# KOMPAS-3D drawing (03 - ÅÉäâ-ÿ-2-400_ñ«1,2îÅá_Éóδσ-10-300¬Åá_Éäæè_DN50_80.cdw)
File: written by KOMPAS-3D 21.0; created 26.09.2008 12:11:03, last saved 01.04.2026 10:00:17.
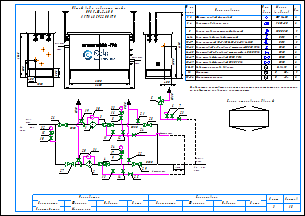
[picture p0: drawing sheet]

Sheets 1-2: A3, landscape

Document properties: Наименование: Макро:21; Автор: RaskoAdmin; Форматы листов документа: 2xA3; Полное имя файла: \\UR38nt01\Departments\КТО\КБ ПУРДГ\Заявки\Прайс-лист на типовые шкафы ГРПШ\ПРДГ_стандарт_20_03_2026\ПРДГ с РДСК\ПРДГ-Ш-2-400_до1,2МПа_Рвых-10-300кПа_РДСК_DN50_80.cdw

Title block, sheet 1: Наименование: Пункт учета газа / ПУГ-Ш-400-Р / ЛГТИ.485922.001ТУ; designation: ЛГТИ.03.4411141; sheet number: 1; Количество листов документа: 2; organisation: ООО "ЭЛЬСТЕР Газэлектроника"; Форматы листов документа: A3; stored path: C:\Рабочие документы\Компас\ПУГ\Схема.cdw; Разработал: Устинов; Проверил: Кошкин; Утвердил: Кошкин
Title block, sheet 2: sheet number: 2; stored path: D:\Рабочие документы\Заявки\ПУРДГ\ПУРДГ-ШУЭО-2-100-Р 4411220.cdw; designation, second copy: ЛГТИ.03.4411141-

Views: Вид 1, Вид 2
Referenced files: wcvoit.frw
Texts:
  Normal
  Вход
  газа
  PDI
  Выход
  Р=     кПа
  DN80
  DN50
  DN20
  Импульс DN20
  ≥5DN
  HYSWLongFangSong
  № на
  схеме
  Усл.
  обозн.
  Марка
  (модель)
  Кол.
  Фильтр газовый фланцевый
  ФГ 16-50
  Регулятор давления газа
  РДCК-50
  Клапан предохранительный сбросной
  КПС DN20
  Кран шаровой газовый латунный
  DN15
  Кран кнопочный VE-РАСКО-НЗ-1,6-G1/2-М20
  Кран шаровой "под приварку" штуцерный DN20 PN16
  Кран шаровой "под приварку" штуцерный п/п DN20 PN16
  Кран шаровой фланцевый DN50 PN16
  Кран шаровой фланцевый DN80 PN16
  Индикатор перепада давления
  Delta 15
  Манометр
  Манометр-напоромер
  0...     МПа
  0...     кПа
  Общий вид и габариты шкафа
  ПРДГ-Ш-2-400
  Выход газа
  Вход газа
  Схема открывания дверей
  Р=        МПа
  logo-rasko-ge.png
  Предприятие изготовитель может заменять комплектующие на аналогичные,
  не ухудшающие заявленных характеристик.
  Должность
  Конструктор
  Фамилия
  Подпись
  Дата
  Согласовано
  Максимкин
  Лист
  Листов
  POLYLINE_STYLE_0.18_RGB_0_0_0
  POLYLINE_STYLE_0.50_RGB_0_0_0
  POLYLINE_STYLE_0.34_RGB_0_0_0
  PHANTOM_RGB_0_0_0_SC_1_THICK_0.18
  K5LT_THIN_RGB_0_0_0_THICK_0.18
  K5LT32769_RGB_0_0_0_THICK_0.18
  K5LT12_RGB_0_0_0_SC_1_THICK_0.18
  K5LT_DASHED_RGB_0_0_0_SC_1_THICK_0.18
  ACISOTGL_RGB_0_0_0_SC_0.8_THICK_0.25
  CONTINUOUS_RGB_0_127_31_THICK_0.3
  CONTINUOUS_RGB_0_0_255_THICK_0.35
  CONTINUOUS_RGB_255_0_0_THICK_0.35
  POLYLINE_STYLE_0.25_RGB_0_0_0
  CONTINUOUS_RGB_0_0_0_THICK_0.5
  POLYLINE_STYLE_0.35_RGB_0_0_255
  CONTINUOUS_RGB_0_0_0_THICK_0.4
  CONTINUOUS_RGB_0_0_0_THICK_0.35
  Без оформления
Dimensions and other numbers on the sheet: 1; 2; 3; 4; 5; 10; 27; 28; 29; 23; 8; 12; 19; 20; 21; 22; 25; 24; 30; 31; 15; 16; 26; 6; 7; 11; 14; 13; 33; 1, 2; 3, 4; 6-14; 9; 15-17; 18-23; 24-25; 26-27; 28-29; 30-31; 32; 33-34; 400; 1050; 500; 305; 2300; 1565; 2600; 17; 34; 1000; 4130; 18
